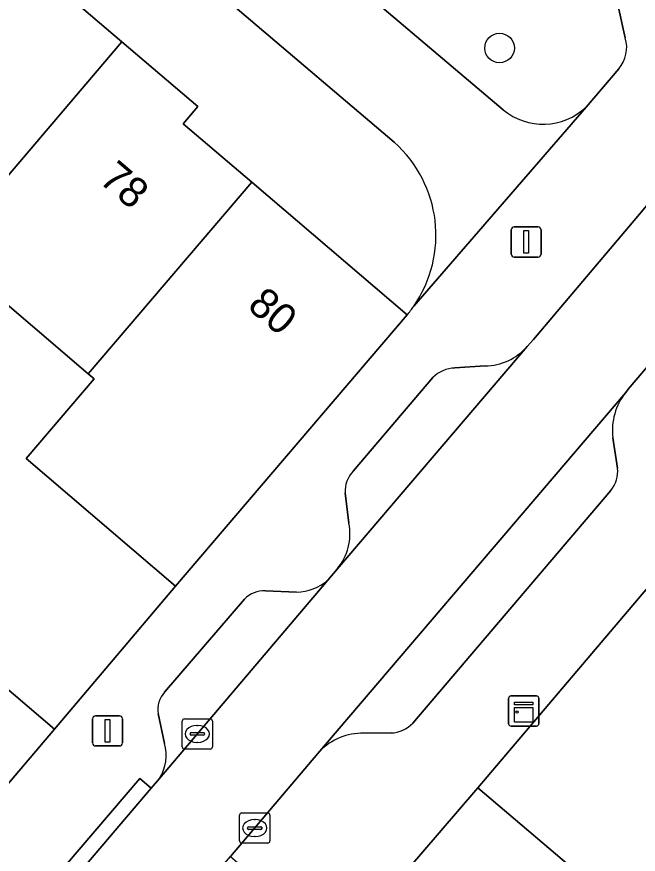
# Model space of a CAD drawing. Extents: x 162523 to 163266, y 381230 to 382050.
# Drawn here: x 163117.61 to 163138.16, y 381710.23 to 381737.94 of the extents above; entities that cross this region are included whole.
import ezdxf

# ---------------------------------------------------------------- set-up
doc = ezdxf.new("R2010")
doc.units = 0
for name, color, linetype in [('IMGEO_Boom', 7, 'Continuous'), ('IMGEO_Erf', 7, 'Continuous'), ('IMGEO_Groenvoorziening', 7, 'Continuous'), ('IMGEO_Kast', 7, 'Continuous'), ('IMGEO_Kolk', 7, 'Continuous'), ('IMGEO_Lichtmast', 7, 'Continuous'), ('IMGEO_Muur', 7, 'Continuous'), ('IMGEO_Pand', 7, 'Continuous'), ('IMGEO_Pand_nummerreeks', 7, 'Continuous'), ('IMGEO_Parkeervlak_open', 7, 'Continuous'), ('IMGEO_Rijbaan_lokaal_open', 7, 'Continuous'), ('IMGEO_Voetpad_open', 7, 'Continuous')]:
    doc.layers.add(name, color=color, linetype=linetype)

msp = doc.modelspace()

# ---------------------------------------------------------------- linework, layer by layer
at = {"layer": 'IMGEO_Boom'}
msp.add_circle((163133.574, 381736.902), 0.489, dxfattribs=at)
at = {"layer": 'IMGEO_Erf'}
for points in [[(163089.77, 381767.094), (163087.717, 381764.463), (163092.672, 381760.272), (163097.34, 381756.323), (163099.585, 381754.424), (163100.163, 381755.108), (163102.513, 381753.12), (163105.073, 381750.954), (163104.55, 381750.336), (163104.939, 381750), (163106.653, 381748.52), (163108.968, 381746.521), (163109.431, 381747.065), (163111.766, 381745.073), (163114.314, 381742.9), (163113.784, 381742.278), (163115.919, 381740.457), (163118.262, 381738.458), (163118.785, 381739.071), (163121.086, 381737.108), (163123.6, 381734.964), (163123.113, 381734.393), (163125.377, 381732.462), (163130.519, 381728.076)], [(163130.093, 381733.784), (163111.007, 381750)], [(163074.342, 381747.088), (163099.35, 381726.253), (163099.521, 381726.46), (163101.013, 381728.271), (163103.811, 381725.967), (163106.605, 381723.666), (163105.489, 381722.312), (163105.113, 381721.855), (163104.892, 381721.626), (163106.779, 381720.008), (163108.744, 381722.385), (163113.498, 381718.331), (163113.794, 381718.677), (163118.851, 381714.364), (163122.861, 381719.099), (163117.916, 381723.317), (163120.164, 381725.953), (163119.97, 381726.12), (163116.272, 381729.275), (163115.192, 381730.195), (163110.545, 381734.153), (163105.858, 381738.144)], [(163156.049, 381691.503), (163151.287, 381695.545), (163151.815, 381696.193), (163146.969, 381700.338), (163148.913, 381702.612), (163144.129, 381706.671), (163139.682, 381710.445), (163139.342, 381710.733), (163137.452, 381708.523), (163136.669, 381709.187), (163132.857, 381712.423), (163127.802, 381706.548), (163128.456, 381705.978), (163132.66, 381702.415), (163131.891, 381701.507), (163135.487, 381698.459), (163134.008, 381696.714), (163145.004, 381687.238), (163140.97, 381682.758), (163159.202, 381667.12)]]:
    msp.add_lwpolyline(points, dxfattribs=at)
for centre, radius, start, end in [((163127.353, 381730.71), 4.118, 325.1776, 48.2973), ((163127.5, 381730.601), 3.936, 320.0956, 325.2598)]:
    msp.add_arc(centre, radius, start, end, dxfattribs=at)
at = {"layer": 'IMGEO_Groenvoorziening'}
for points in [[(163136.44, 381741.787), (163131.018, 381746.354), (163126.461, 381740.986), (163133.696, 381734.86)], [(163137.733, 381737.235), (163136.866, 381741.147)], [(163136.435, 381734.951), (163137.516, 381736.21)]]:
    msp.add_lwpolyline(points, dxfattribs=at)
for centre, radius, start, end in [((163136.683, 381736.922), 1.096, 319.4803, 16.6129), ((163135.015, 381736.439), 2.057, 230.1362, 313.6695)]:
    msp.add_arc(centre, radius, start, end, dxfattribs=at)
at = {"layer": 'IMGEO_Kast'}
for p, q in [((163133.95, 381715.469), (163134.791, 381715.469)), ((163134.791, 381715.469), (163133.95, 381715.469)), ((163133.875, 381714.544), (163133.875, 381715.385)), ((163133.875, 381715.385), (163133.875, 381714.544)), ((163134.875, 381715.394), (163134.875, 381714.553)), ((163134.875, 381714.553), (163134.875, 381715.394)), ((163134.8, 381714.469), (163133.959, 381714.469)), ((163133.959, 381714.469), (163134.8, 381714.469))]:
    msp.add_line(p, q, dxfattribs=at)
for points in [[(163134.07, 381715.259), (163134.67, 381715.259), (163134.67, 381715.174), (163134.07, 381715.174), (163134.07, 381715.259)], [(163134.07, 381715.084), (163134.67, 381715.084), (163134.67, 381714.595), (163134.07, 381714.595), (163134.07, 381715.084)]]:
    msp.add_lwpolyline(points, dxfattribs=at)
msp.add_circle((163134.154, 381714.933), 0.0377, dxfattribs=at)
for centre, start, end in [((163133.953, 381715.391), 92.4484, 184.2845), ((163133.953, 381715.391), 92.4484, 184.2845), ((163134.797, 381715.391), 2.4484, 94.2845), ((163134.797, 381715.391), 2.4484, 94.2845), ((163133.953, 381714.547), 182.4484, 274.2845), ((163133.953, 381714.547), 182.4484, 274.2845), ((163134.797, 381714.547), 272.4484, 4.2845), ((163134.797, 381714.547), 272.4484, 4.2845)]:
    msp.add_arc(centre, 0.0779, start, end, dxfattribs=at)
at = {"layer": 'IMGEO_Kolk'}
for p, q in [((163123.078, 381713.784), (163123.078, 381714.636)), ((163123.153, 381714.71), (163124.005, 381714.71)), ((163124.079, 381714.636), (163124.079, 381713.784)), ((163123.566, 381714.49), (163123.591, 381714.49)), ((163123.337, 381714.204), (163123.337, 381714.216)), ((163123.775, 381714.167), (163123.377, 381714.167)), ((163123.38, 381714.253), (163123.778, 381714.253)), ((163123.821, 381714.216), (163123.821, 381714.204)), ((163123.589, 381713.93), (163123.564, 381713.93)), ((163124.005, 381713.71), (163123.153, 381713.71)), ((163125.053, 381711.596), (163125.905, 381711.596)), ((163124.978, 381710.67), (163124.978, 381711.522)), ((163125.466, 381711.376), (163125.491, 381711.376)), ((163125.979, 381711.522), (163125.979, 381710.67)), ((163125.237, 381711.09), (163125.237, 381711.102)), ((163125.675, 381711.053), (163125.277, 381711.053)), ((163125.28, 381711.139), (163125.678, 381711.139)), ((163125.721, 381711.102), (163125.721, 381711.09)), ((163125.489, 381710.816), (163125.464, 381710.816)), ((163125.905, 381710.596), (163125.053, 381710.596))]:
    msp.add_line(p, q, dxfattribs=at)
for points in [[(163123.078, 381713.784), (163123.078, 381714.636)], [(163123.153, 381714.71), (163124.005, 381714.71)], [(163124.079, 381714.636), (163124.079, 381713.784)], [(163124.005, 381713.71), (163123.153, 381713.71)], [(163125.053, 381711.596), (163125.905, 381711.596)], [(163124.978, 381710.67), (163124.978, 381711.522)], [(163125.979, 381711.522), (163125.979, 381710.67)], [(163125.905, 381710.596), (163125.053, 381710.596)]]:
    msp.add_lwpolyline(points, dxfattribs=at)
for centre, radius, start, end in [((163123.155, 381714.634), 0.0765, 91.552, 178.448), ((163123.155, 381714.634), 0.0765, 91.552, 178.448), ((163124.003, 381714.634), 0.0765, 1.552, 88.448), ((163124.003, 381714.634), 0.0765, 1.552, 88.448), ((163123.377, 381714.213), 0.0403, 85.8775, 175.7526), ((163123.374, 381714.203), 0.0366, 178.938, 274.7102), ((163123.778, 381714.21), 0.043, 264.8664, 352.4533), ((163123.782, 381714.215), 0.0386, 1.7309, 96.639), ((163123.155, 381713.786), 0.0765, 181.552, 268.448), ((163123.155, 381713.786), 0.0765, 181.552, 268.448), ((163124.003, 381713.786), 0.0765, 271.552, 358.448), ((163124.003, 381713.786), 0.0765, 271.552, 358.448), ((163125.055, 381711.52), 0.0765, 91.552, 178.448), ((163125.055, 381711.52), 0.0765, 91.552, 178.448), ((163125.903, 381711.52), 0.0765, 1.552, 88.448), ((163125.903, 381711.52), 0.0765, 1.552, 88.448), ((163125.277, 381711.099), 0.0403, 85.8775, 175.7526), ((163125.274, 381711.089), 0.0366, 178.938, 274.7102), ((163125.678, 381711.096), 0.043, 264.8664, 352.4533), ((163125.682, 381711.101), 0.0386, 1.7309, 96.639), ((163125.055, 381710.672), 0.0765, 181.552, 268.448), ((163125.055, 381710.672), 0.0765, 181.552, 268.448), ((163125.903, 381710.672), 0.0765, 271.552, 358.448), ((163125.903, 381710.672), 0.0765, 271.552, 358.448)]:
    msp.add_arc(centre, radius, start, end, dxfattribs=at)
for centre, major_axis, ratio, start_param, end_param in [((163123.565, 381714.21), (-0.387, 0.002), 0.722429, 4.712389, 7.853982), ((163123.59, 381714.21), (-0.39, 0.002), 0.717154, 1.570796, 4.712389), ((163125.465, 381711.096), (-0.387, 0.002), 0.722429, 4.712389, 7.853982), ((163125.49, 381711.096), (-0.39, 0.002), 0.717154, 1.570796, 4.712389)]:
    msp.add_ellipse(centre, major_axis=major_axis, ratio=ratio, start_param=start_param, end_param=end_param, dxfattribs=at)
at = {"layer": 'IMGEO_Lichtmast'}
for p, q in [((163134.061, 381730.987), (163134.851, 381730.987)), ((163134.851, 381730.987), (163134.061, 381730.987)), ((163133.961, 381730.087), (163133.961, 381730.887)), ((163133.961, 381730.887), (163133.961, 381730.087)), ((163134.951, 381730.887), (163134.951, 381730.087)), ((163134.951, 381730.087), (163134.951, 381730.887)), ((163134.851, 381729.987), (163134.061, 381729.987)), ((163134.061, 381729.987), (163134.851, 381729.987)), ((163120.112, 381713.911), (163120.112, 381714.711)), ((163120.112, 381714.711), (163120.112, 381713.911)), ((163120.212, 381714.811), (163121.002, 381714.811)), ((163121.002, 381714.811), (163120.212, 381714.811)), ((163121.102, 381714.711), (163121.102, 381713.911)), ((163121.102, 381713.911), (163121.102, 381714.711)), ((163121.002, 381713.811), (163120.212, 381713.811)), ((163120.212, 381713.811), (163121.002, 381713.811))]:
    msp.add_line(p, q, dxfattribs=at)
for points in [[(163134.381, 381730.862), (163134.531, 381730.862), (163134.531, 381730.112), (163134.381, 381730.112), (163134.381, 381730.862)], [(163120.532, 381714.686), (163120.682, 381714.686), (163120.682, 381713.936), (163120.532, 381713.936), (163120.532, 381714.686)]]:
    msp.add_lwpolyline(points, dxfattribs=at)
for centre, start, end in [((163134.061, 381730.887), 90, 180), ((163134.061, 381730.887), 90, 180), ((163134.851, 381730.887), 0, 90), ((163134.851, 381730.887), 360, 90), ((163134.061, 381730.087), 180, 270), ((163134.061, 381730.087), 180, 270), ((163134.851, 381730.087), 270, 0), ((163134.851, 381730.087), 270, 0), ((163120.212, 381714.711), 90, 180), ((163120.212, 381714.711), 90, 180), ((163121.002, 381714.711), 0, 90), ((163121.002, 381714.711), 360, 90), ((163120.212, 381713.911), 180, 270), ((163120.212, 381713.911), 180, 270), ((163121.002, 381713.911), 270, 0), ((163121.002, 381713.911), 270, 0)]:
    msp.add_arc(centre, 0.1, start, end, dxfattribs=at)
at = {"layer": 'IMGEO_Muur'}
for points in [[(163122.861, 381719.099), (163118.851, 381714.364)], [(163128.456, 381705.978), (163127.802, 381706.548), (163132.857, 381712.423)]]:
    msp.add_lwpolyline(points, dxfattribs=at)
at = {"layer": 'IMGEO_Pand'}
for points in [[(163115.192, 381730.195), (163121.086, 381737.108), (163118.785, 381739.071), (163118.262, 381738.458), (163115.919, 381740.457), (163110.545, 381734.153)], [(163125.377, 381732.462), (163123.113, 381734.393), (163123.6, 381734.964), (163121.086, 381737.108), (163115.192, 381730.195), (163116.272, 381729.275), (163119.97, 381726.12)], [(163125.377, 381732.462), (163119.97, 381726.12), (163120.164, 381725.953), (163117.916, 381723.317), (163122.861, 381719.099), (163130.519, 381728.076)], [(163144.186, 381716.396), (163143.99, 381716.563), (163144.569, 381717.246), (163142.481, 381719.018), (163141.934, 381718.394), (163139.589, 381720.366), (163132.857, 381712.423), (163136.669, 381709.187), (163137.452, 381708.523), (163139.342, 381710.733)], [(163113.794, 381718.677), (163113.498, 381718.331), (163111.497, 381715.984), (163116.554, 381711.671), (163118.851, 381714.364)]]:
    msp.add_lwpolyline(points, close=True, dxfattribs=at)
at = {"layer": 'IMGEO_Parkeervlak_open'}
for points in [[(163128.2, 381719.664), (163134.485, 381727.029)], [(163133.095, 381726.385), (163132.095, 381726.317)], [(163131.369, 381726.001), (163128.736, 381722.903)], [(163137.751, 381725.507), (163127.564, 381713.568)], [(163137.475, 381723.002), (163137.325, 381724.008)], [(163128.463, 381722.182), (163128.591, 381721.188)], [(163130.702, 381714.569), (163137.254, 381722.267)], [(163122.331, 381712.736), (163127.893, 381719.302)], [(163126.859, 381718.9), (163125.834, 381718.942)], [(163125.134, 381718.667), (163122.494, 381715.594)], [(163122.281, 381714.882), (163122.498, 381713.894)], [(163128.984, 381714.233), (163129.989, 381714.242)]]:
    msp.add_lwpolyline(points, dxfattribs=at)
for centre, radius, start, end in [((163133.073, 381728.254), 1.869, 270.6599, 319.0575), ((163132.127, 381725.25), 1.067, 91.7442, 135.2991), ((163139.271, 381724.265), 1.963, 140.7494, 187.5214), ((163136.518, 381722.889), 0.963, 319.7884, 6.7416), ((163129.433, 381722.227), 0.971, 135.8794, 182.6432), ((163126.81, 381720.833), 1.816, 319.9397, 11.2812), ((163126.83, 381720.506), 1.607, 271.048, 311.4423), ((163125.775, 381718.064), 0.88, 86.1478, 136.7476), ((163123.177, 381715.002), 0.904, 139.0799, 187.6102), ((163129.961, 381715.245), 1.003, 271.6177, 317.6571), ((163129.045, 381712.255), 1.979, 91.7535, 138.4349), ((163121.096, 381713.505), 1.455, 328.0784, 15.509)]:
    msp.add_arc(centre, radius, start, end, dxfattribs=at)
at = {"layer": 'IMGEO_Rijbaan_lokaal_open'}
msp.add_lwpolyline([(163137.751, 381725.507), (163137.833, 381725.621), (163138.592, 381726.507), (163141.631, 381730.06), (163138.98, 381732.328), (163135.963, 381728.758), (163134.7, 381727.262), (163134.485, 381727.029), (163128.2, 381719.664), (163127.893, 381719.302), (163122.331, 381712.736), (163122.057, 381712.412), (163119.601, 381709.536), (163112.378, 381701.07), (163115.024, 381698.823), (163122.133, 381707.199), (163124.68, 381710.151), (163127.564, 381713.568)], close=True, dxfattribs=at)
at = {"layer": 'IMGEO_Voetpad_open'}
for points in [[(163133.696, 381734.86), (163126.461, 381740.986), (163125, 381742.254), (163115.873, 381750), (163113.895, 381751.679), (163112.336, 381752.956), (163101.292, 381762.38), (163099.745, 381763.656), (163091.979, 381770.287)], [(163090.727, 381767.231), (163111.007, 381750), (163130.093, 381733.784)], [(163136.866, 381741.147), (163137.733, 381737.235)], [(163137.516, 381736.21), (163136.435, 381734.951), (163130.734, 381728.358)], [(163130.734, 381728.358), (163136.435, 381734.951)], [(163134.485, 381727.029), (163134.7, 381727.262), (163135.963, 381728.758), (163138.98, 381732.328), (163140.663, 381734.293)], [(163143.288, 381731.935), (163141.631, 381730.06), (163138.592, 381726.507), (163137.833, 381725.621), (163137.751, 381725.507)], [(163130.519, 381728.076), (163122.861, 381719.099), (163118.851, 381714.364), (163116.554, 381711.671), (163115.395, 381710.308), (163083.389, 381672.655), (163061.302, 381646.699), (163059.389, 381644.452), (163043.741, 381626.048), (163046.532, 381623.783), (163047.165, 381624.502)], [(163123.788, 381703.302), (163124.567, 381702.644), (163125.584, 381703.861), (163126.209, 381703.326), (163128.456, 381705.978), (163127.802, 381706.548), (163132.857, 381712.423), (163139.589, 381720.366), (163142.194, 381723.423), (163145.337, 381726.7)], [(163132.095, 381726.317), (163133.095, 381726.385)], [(163128.736, 381722.903), (163131.369, 381726.001)], [(163137.325, 381724.008), (163137.475, 381723.002)], [(163128.591, 381721.188), (163128.463, 381722.182)], [(163137.254, 381722.267), (163130.702, 381714.569)], [(163127.893, 381719.302), (163128.2, 381719.664)], [(163125.834, 381718.942), (163126.859, 381718.9)], [(163122.494, 381715.594), (163125.134, 381718.667)], [(163122.498, 381713.894), (163122.281, 381714.882)], [(163129.989, 381714.242), (163128.984, 381714.233)], [(163127.564, 381713.568), (163124.68, 381710.151), (163125.058, 381709.825), (163122.573, 381706.946), (163122.133, 381707.199)], [(163119.601, 381709.536), (163119.221, 381709.86), (163121.677, 381712.736), (163122.057, 381712.412), (163122.331, 381712.736)]]:
    msp.add_lwpolyline(points, dxfattribs=at)
msp.add_lwpolyline([(163119.601, 381709.536), (163122.057, 381712.412), (163121.677, 381712.736), (163119.221, 381709.86)], close=True, dxfattribs=at)
for centre, radius, start, end in [((163136.683, 381736.922), 1.096, 319.4803, 16.6129), ((163135.015, 381736.439), 2.057, 230.1362, 313.6695), ((163127.353, 381730.71), 4.118, 325.1776, 48.2973), ((163127.5, 381730.601), 3.936, 320.0956, 325.2598), ((163133.073, 381728.254), 1.869, 270.6599, 319.0575), ((163132.127, 381725.25), 1.067, 91.7442, 135.2991), ((163139.271, 381724.265), 1.963, 140.7494, 187.5214), ((163136.518, 381722.889), 0.963, 319.7884, 6.7416), ((163129.433, 381722.227), 0.971, 135.8794, 182.6432), ((163126.81, 381720.833), 1.816, 319.9397, 11.2812), ((163126.83, 381720.506), 1.607, 271.048, 311.4423), ((163125.775, 381718.064), 0.88, 86.1478, 136.7476), ((163123.177, 381715.002), 0.904, 139.0799, 187.6102), ((163129.961, 381715.245), 1.003, 271.6177, 317.6571), ((163129.045, 381712.255), 1.979, 91.7535, 138.4349), ((163121.096, 381713.505), 1.455, 328.0784, 15.509)]:
    msp.add_arc(centre, radius, start, end, dxfattribs=at)

# ---------------------------------------------------------------- texts
at = {"layer": 'IMGEO_Pand_nummerreeks'}
for s, rotation, p in [('78', 319.6003, (163120.287, 381732.486)), ('80', 319.5372, (163125.193, 381728.309))]:
    msp.add_text(s, height=1, rotation=rotation, dxfattribs=at).set_placement(p)

doc.saveas('drawing.dxf')
